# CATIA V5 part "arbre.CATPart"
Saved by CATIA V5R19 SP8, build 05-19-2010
Part number: arbre
Bounding box of the stored display mesh (mm): x 12.851 to 79, y 246.964 to 256.964, z 83.354 to 93.354
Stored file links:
  G:\EU_thinkMotion\CFAO_2010\MMS_groupe3\MMS_groupe3\A reprendre\amenand\amenand\arbre.CATPart
  F:\thinkmotion CFAO v12.1\essuie_glace.CATProduct
  G:\EU_thinkMotion\CFAO_2010\MMS_groupe3\MMS_groupe3\A reprendre\amenand\amenand\balai.CATPart
  G:\EU_thinkMotion\CFAO_2010\MMS_groupe3\MMS_groupe3\A reprendre\amenand\amenand\coulisseau.CATPart
  G:\EU_thinkMotion\CFAO_2010\MMS_groupe3\MMS_groupe3\A reprendre\amenand\amenand\bielle.CATPart
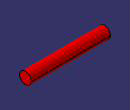
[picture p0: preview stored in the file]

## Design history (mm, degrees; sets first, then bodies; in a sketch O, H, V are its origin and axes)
Set1
  Point1: linked copy from another document
  DatumSurface1: linked copy from another document
  Plane1: linked copy from another document
Body1 (main body)
  Sketch1 on Plane1, origin (79, 0, 0), H (0, 1, 0), V (0, 0, 1)
    circle A1 centre (251.964, 88.354) radius 5
    point P1 (251.964, 88.354)
    reference projected point E1 (251.964, 88.354) from Point1
    radius A1 = 5
    coincidence: P1 E1
  Pad1: profile Sketch1, direction (-1, 0, 0), up to face of DatumSurface1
